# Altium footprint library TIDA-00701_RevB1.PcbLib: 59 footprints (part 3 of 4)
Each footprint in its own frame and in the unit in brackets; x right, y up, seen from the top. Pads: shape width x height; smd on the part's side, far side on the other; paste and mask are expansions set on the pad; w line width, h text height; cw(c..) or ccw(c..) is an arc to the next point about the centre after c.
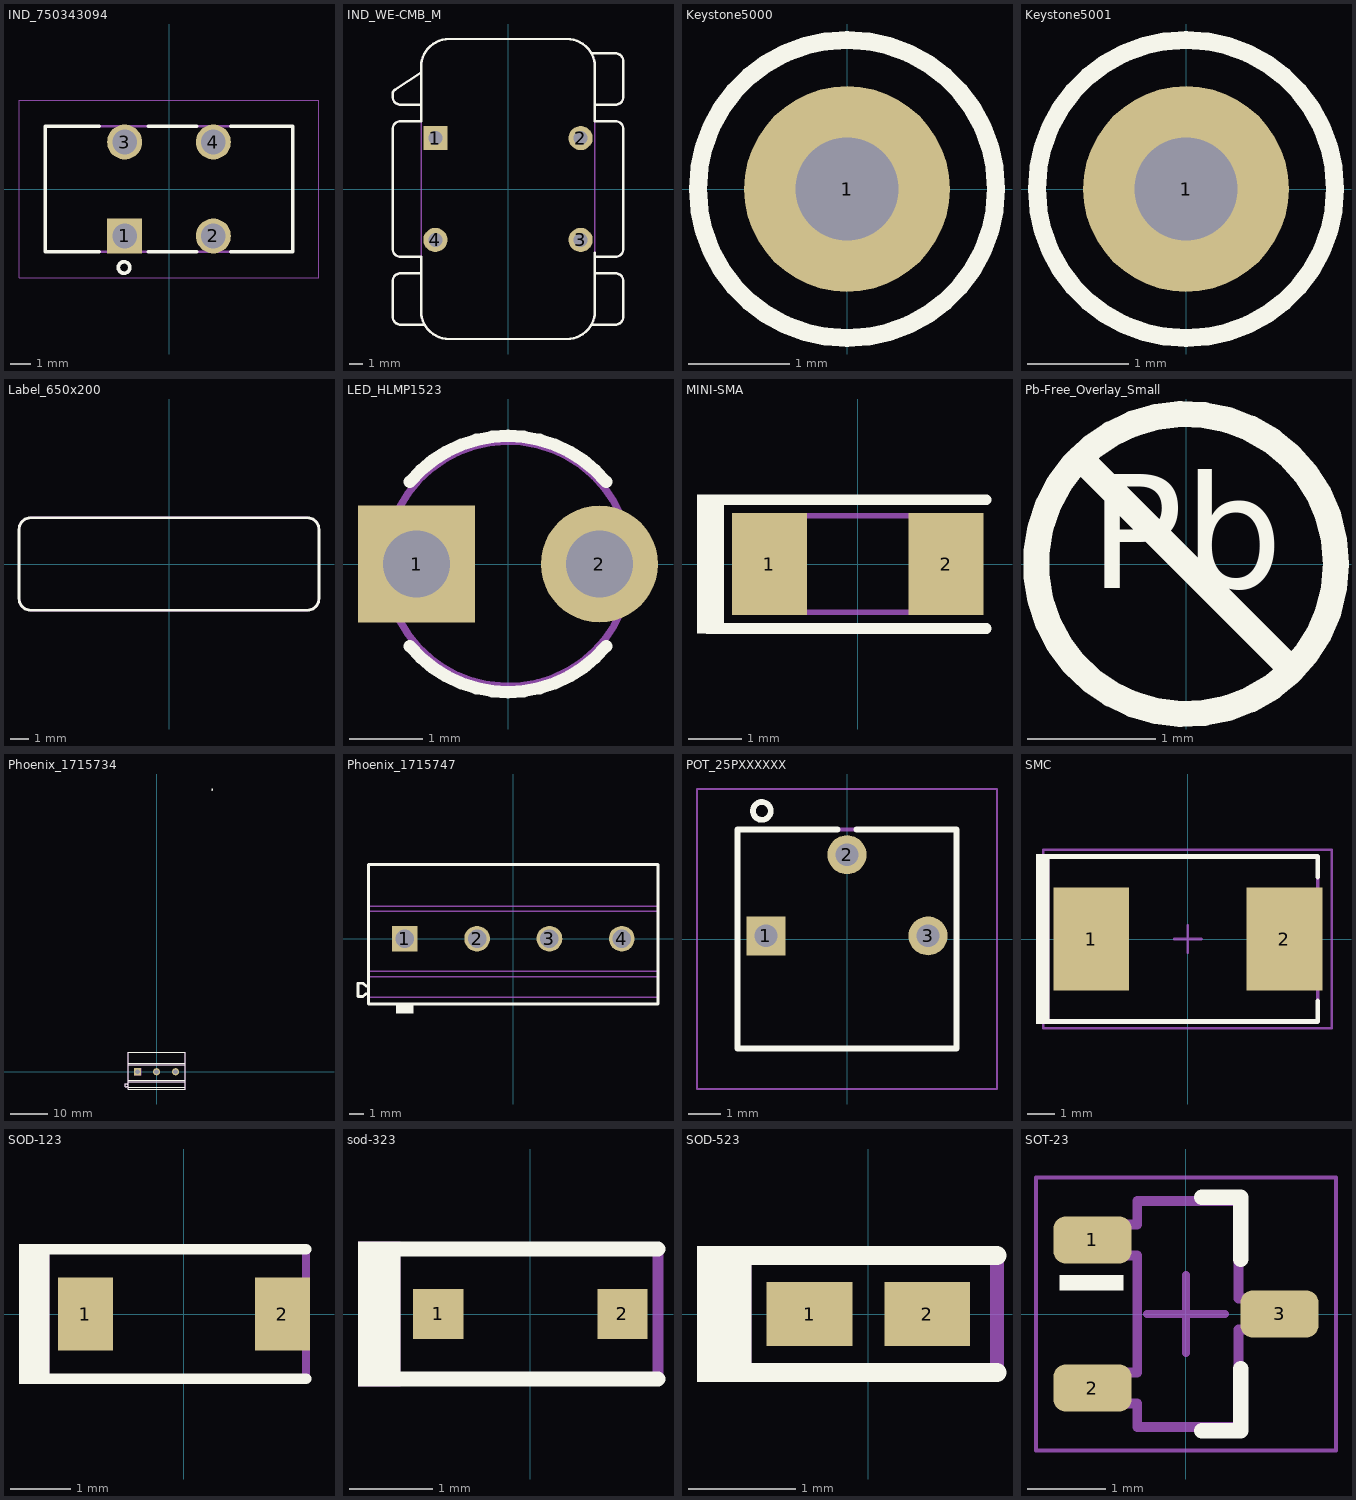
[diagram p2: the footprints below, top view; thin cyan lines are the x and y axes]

## IND_750343094 [mm] "INDUCTOR, TH-4P"
height 13.06
pads (4):
  rect 1.7x1.7 / inner round 1.7 / far side rect 1.7x1.7 hole 1.2: 1(-2.16,-2.285)
  round 1.7 hole 1.2: 2(2.16,-2.285) 3(-2.16,2.285) 4(2.16,2.285)
Top Overlay:
  circle w0.178: c-2.184,-3.82 r0.279
  lines w0.178: -3.4,-3.05 -6.03,-3.05 -6.03,3.05 -3.4,3.05 ; -1,-3.05 1.35,-3.05 ; -1,3.05 1.35,3.05 ; 3,-3.05 6.03,-3.05 6.03,3.05 3,3.05
Bottom Overlay:
  lines w0.178: -6.03,-3.048 -5.302,-3.048 ; -6.03,-1.966 -6.03,-0.95 ; -6.03,0.034 -6.03,1.05 ; -6.03,2.034 -6.03,3.05 -4.887,3.05 ; -4.445,-3.048 -3.302,-3.048 ; -4.03,3.05 -2.92,3.05 ; -1.35,3.05 1.27,3.048 ; -1,-3.05 1.35,-3.05 ; 2.92,-3.05 4.03,-3.05 ; 3.175,3.048 4.445,3.048 ; 4.887,-3.05 6.03,-3.05 6.03,-2.034 ; 5.302,3.048 6.03,3.048 ; 6.03,-1.05 6.03,-0.034 ; 6.03,0.95 6.03,1.966
Mechanical 5:
  circle w0.127: c-2.184,-3.82 r0.279
  lines w0.127: -6.03,-3.05 6.03,-3.05 6.03,3.05 -6.03,3.05 -6.03,-3.05
  text ".Designator" at -1.524,-0.508 h0.89
Mechanical 15:
  lines w0.05: -7.3,-4.32 7.3,-4.32 7.3,4.32 -7.3,4.32 -7.3,-4.32
Mechanical 17:
  text "LEAD LENGHT: 2.81MM" at -13.843,-6.604 h1.52
3D body: height 13.06, standoff 0, extent -6.03,-3.05 6.03,3.05

## IND_WE-CMB_M [mil] "Wurth"
height 1102.36
pads (4):
  rect 70x70 hole 40: 1(-210.63,147.64)
  round 70 hole 40: 2(210.63,147.64) 3(210.63,-147.64) 4(-210.63,-147.64)
Top Overlay:
  lines w7: -251.97,-354.33 ccw(c-171.26,-354.33) -171.26,-435.04 171.26,-435.04 ccw(c171.26,-354.33) 251.97,-354.33 251.97,-346.59 251.97,-323.7 251.97,-286.66 251.97,-237.09 251.97,-184.41 ; -251.97,-354.08 -251.97,-349.11 -251.97,-328.88 -251.97,-294.28 -251.97,-246.81 -251.97,-206.08 -251.97,-203.51 -251.97,-198.82 ; -251.97,-244.09 -311.02,-244.09 ccw(c-311.02,-267.72) -334.65,-267.72 -334.65,-370.08 ccw(c-311.02,-370.08) -311.02,-393.7 -241.67,-393.7 ; -251.97,-196.85 -311.02,-196.85 cw(c-311.02,-173.23) -334.65,-173.23 -334.65,173.23 cw(c-311.02,173.23) -311.02,196.85 -251.97,196.85 ; -251.97,198.82 -251.97,203.51 -251.97,206.08 -251.97,246.81 -251.97,294.28 -251.97,328.88 -251.97,349.11 -251.97,354.08 ; -251.97,244.09 -311.02,244.09 cw(c-311.02,267.72) -334.65,267.72 -334.65,274.98 cw(c-318.9,274.98) -327.56,288.13 -251.97,337.93 ; -251.97,354.33 cw(c-171.26,354.33) -171.26,435.04 171.26,435.04 cw(c171.26,354.33) 251.97,354.33 251.97,346.59 251.97,323.7 251.97,286.66 251.97,196.85 311.02,196.85 cw(c311.02,173.23) 334.65,173.23 334.65,-173.23 cw(c311.02,-173.23) 311.02,-196.85 251.97,-196.85 ; 241.71,-393.7 311.02,-393.7 ccw(c311.02,-370.08) 334.65,-370.08 334.65,-267.72 ccw(c311.02,-267.72) 311.02,-244.09 251.97,-244.09 ; 241.71,393.7 311.02,393.7 cw(c311.02,370.08) 334.65,370.08 334.65,267.72 cw(c311.02,267.72) 311.02,244.09 251.97,244.09
Mechanical 5:
  lines w5: -251.97,-354.33 ccw(c-171.26,-354.33) -171.26,-435.04 171.26,-435.04 ccw(c171.26,-354.33) 251.97,-354.33 251.97,-346.59 251.97,-323.7 251.97,-286.66 251.97,-237.09 251.97,-184.41 251.97,-165.23 251.97,237.09 251.97,286.66 251.97,323.7 251.97,346.59 251.97,354.33 ccw(c171.26,354.33) 171.26,435.04 -171.26,435.04 ccw(c-171.26,354.33) -251.97,354.33 ; -251.97,-354.08 -251.97,-349.11 -251.97,-328.88 -251.97,-294.28 -251.97,-246.81 -251.97,-206.08 -251.97,-203.51 -251.97,-198.82 -251.97,-165.23 -251.97,198.82 -251.97,203.51 -251.97,206.08 -251.97,246.81 -251.97,294.28 -251.97,328.88 -251.97,349.11 -251.97,354.08 ; -251.97,-244.09 -311.02,-244.09 ccw(c-311.02,-267.72) -334.65,-267.72 -334.65,-370.08 ccw(c-311.02,-370.08) -311.02,-393.7 -241.67,-393.7 ; -251.97,-196.85 -311.02,-196.85 cw(c-311.02,-173.23) -334.65,-173.23 -334.65,173.23 cw(c-311.02,173.23) -311.02,196.85 -251.97,196.85 ; -251.97,244.09 -311.02,244.09 cw(c-311.02,267.72) -334.65,267.72 -334.65,274.98 cw(c-318.9,274.98) -327.56,288.13 -251.97,337.93 ; 241.71,-393.7 311.02,-393.7 ccw(c311.02,-370.08) 334.65,-370.08 334.65,-267.72 ccw(c311.02,-267.72) 311.02,-244.09 251.97,-244.09 ; 241.71,393.7 311.02,393.7 cw(c311.02,370.08) 334.65,370.08 334.65,267.72 cw(c311.02,267.72) 311.02,244.09 251.97,244.09 ; 251.97,-196.85 311.02,-196.85 ccw(c311.02,-173.23) 334.65,-173.23 334.65,173.23 ccw(c311.02,173.23) 311.02,196.85 251.97,196.85
  text ".Designator" at 6,21 h35
3D body: height 1043.91, standoff -117.51, extent -334.65,-393.69 334.64,393.71

## Keystone5000 [mil] "For Keystone 500x miniature loop terminals"
height 181.1
pads (1):
  round 80 hole 40: 1(0,0)
Top Overlay:
  circle w7: c0,0 r58
Mechanical 5:
  circle w5: c0,0 r58.31
  text ".Designator" at -164,5 h35
3D body: height 181.97, standoff -118.11, extent -49,-49 49.04,49.24

## Keystone5001 [mil] "For Keystone 500x miniature loop terminals"
height 181.1
pads (1):
  round 80 hole 40: 1(0,0)
Top Overlay:
  circle w7: c0,0 r58
Mechanical 5:
  circle w5: c0,0 r58.31
  text ".Designator" at -105,66 h35
3D body: height 181.97, standoff -118.11, extent -49,-49 49.04,49.24

## Label_650x200 [mm] "Thermal Transfer Label"
height 0.025
Top Overlay:
  lines w0.152: -8.255,-1.905 ccw(c-7.62,-1.905) -7.62,-2.54 7.62,-2.54 ccw(c7.62,-1.905) 8.255,-1.905 8.255,1.905 ccw(c7.62,1.905) 7.62,2.54 -7.62,2.54 ccw(c-7.62,1.905) -8.255,1.905 -8.255,-1.905
Mechanical 5:
  lines w0.127: -8.255,-1.905 ccw(c-7.62,-1.905) -7.62,-2.54 7.62,-2.54 ccw(c7.62,-1.905) 8.255,-1.905 8.255,1.905 ccw(c7.62,1.905) 7.62,2.54 -7.62,2.54 ccw(c-7.62,1.905) -8.255,1.905 -8.255,-1.905
  text ".Designator" at -1.524,-0.508 h0.89
3D body: height 0.03, standoff 0, extent -8.268,-2.553 8.268,2.553

## LED_HLMP1523 [mm] "Everlight Electronics"
height 4.8
pads (2):
  rect 1.6x1.6 hole 0.914: 1(-1.25,0)
  round 1.6 hole 0.914: 2(1.25,0)
Top Overlay:
  lines w0.17: -1.341,-1.125 ccw(c0,0) 1.341,-1.125 ; -1.341,1.125 cw(c0,0) 1.341,1.125
Mechanical 5:
  lines w0.1: -1.57,-0.571 ccw(c0.004,0.002) -1.57,0.575 -1.57,-0.571
  text ".Designator" at 0.305,-0.635 h0.89
3D body: height 6.2, standoff -4.86, extent -1.6,-1.675 1.675,1.675

## MINI-SMA [mm] "COMCHIP"
height 1.45
pads (2):
  rect 1.4x1.9 smd: 1(-1.65,0) 2(1.65,0)
Top Overlay:
  rectangle: -2.999,-1.298 -2.5,1.302
  lines w0.2: -2.8,-1.2 2.4,-1.2 ; -2.8,1.2 2.4,1.2
Mechanical 5:
  rectangle: -1.999,-0.898 -1.299,0.902
  lines w0.1: -2,-0.9 -2,0.9 2,0.9 2,-0.9 0,-0.9 -1.5,-0.9 -2,-0.9
  text ".Designator" at 0.973,0.423 h0.89
3D body: height 1.7, standoff 0, extent -1.95,-0.9 1.95,0.9

## Pb-Free_Overlay_Small [mm]
Top Overlay:
  circle w0.203: c0,0 r1.168
  lines w0.203: -0.826,0.826 0.826,-0.826
  text "Pb" at -0.752,-0.48 h1.52

## Phoenix_1715734 [mm] "Phoenix"
height 13.8
pads (3):
  rect 1.9x1.9 hole 1.321: 1(-5.08,0)
  round 1.9 hole 1.321: 2(0,0) 3(5.08,0)
Top Overlay:
  circle w0.152: c14.834,75.362 r0.152
  lines w0.2: -7.62,-3.869 -7.787,-3.869 -8.019,-4.064 -8.361,-4.064 -8.361,-3.136 -8.019,-3.136 -7.787,-3.331 -7.62,-3.331 ; -7.62,-4.1 7.62,-4.1 ; -7.62,-4.1 -7.62,-4.6 7.62,-4.6 7.62,-4.1 ; -7.62,-4.1 -7.62,-2.672 ; -7.62,-2.672 7.62,-2.672 ; -7.62,-2.672 -7.62,-2.283 ; -7.62,-2.283 7.62,-2.283 ; -7.62,-2.283 -7.62,1.909 ; -7.62,1.909 7.62,1.909 ; -7.62,1.909 -7.62,2.29 ; -7.62,2.29 7.62,2.29 ; -7.62,2.29 -7.62,5.2 7.62,5.2 7.62,2.29 ; 7.62,-4.1 7.62,-2.672 ; 7.62,-2.672 7.62,-2.283 ; 7.62,-2.283 7.62,1.909 ; 7.62,1.909 7.62,2.29
Mechanical 5:
  region: -6.025,0.95 -4.125,0.95 -4.125,-0.95 -6.025,-0.95
  lines w0.127: -7.62,-3.869 -7.787,-3.869 -8.019,-4.064 -8.361,-4.064 -8.361,-3.136 -8.019,-3.136 -7.787,-3.331 -7.62,-3.331 ; -7.62,-4.1 -7.62,-2.672 ; -7.62,-4.1 -7.62,-4.6 7.62,-4.6 7.62,-4.1 ; -7.62,-4.1 7.62,-4.1 ; -7.62,-2.672 -7.62,-2.283 ; -7.62,-2.672 7.62,-2.672 ; -7.62,-2.283 -7.62,1.909 ; -7.62,-2.283 7.62,-2.283 ; -7.62,1.909 -7.62,2.29 ; -7.62,1.909 7.62,1.909 ; -7.62,2.29 -7.62,5.2 7.62,5.2 7.62,2.29 ; -7.62,2.29 7.62,2.29 ; 7.62,-4.1 7.62,-2.672 ; 7.62,-2.672 7.62,-2.283 ; 7.62,-2.283 7.62,1.909 ; 7.62,1.909 7.62,2.29
  text ".Designator" at -2.21,0.33 h0.89
3D body: height 14.2, standoff -3.5, extent -8.361,-4.6 7.62,5.2

## Phoenix_1715747 [mm] "Terminal Block, 5.08mm, 4x1, TH"
height 13.8
pads (4):
  rect 1.8x1.8 hole 1.3: 1(-7.62,0)
  round 1.8 hole 1.3: 2(-2.54,0) 3(2.54,0) 4(7.62,0)
Top Overlay:
  rectangle: -8.25,-5.25 -7,-4.599
  lines w0.2: -10.16,-3.869 -10.327,-3.869 -10.559,-4.064 -10.901,-4.064 -10.901,-3.136 -10.559,-3.136 -10.327,-3.331 -10.16,-3.331 ; -10.16,-4.6 -10.16,5.2 10.16,5.2 10.16,-4.6 -10.16,-4.6
Mechanical 5:
  lines w0.1: -10.16,-4.1 10.16,-4.1 ; -10.16,-3.869 -10.327,-3.869 -10.559,-4.064 -10.901,-4.064 -10.901,-3.136 -10.559,-3.136 -10.327,-3.331 -10.16,-3.331 ; -10.16,-2.672 10.16,-2.672 ; -10.16,-2.283 10.16,-2.283 ; -10.16,1.909 10.16,1.909 ; -10.16,2.29 10.16,2.29 ; -10.16,-4.6 10.16,-4.6 10.16,5.2 -10.16,5.2 -10.16,-4.6
  text ".Designator" at -0.559,0.66 h0.89
3D body: height 14.2, standoff -3.5, extent -10.901,-4.6 10.16,5.2

## POT_25PXXXXXX [mm] "Potentiometer, 25p series, through hole, 3 pin"
height 5.13
pads (3):
  rect 1.222x1.222 hole 0.714: 1(-2.54,0.1)
  round 1.222 hole 0.714: 2(0,2.64) 3(2.54,0.1)
Top Overlay:
  circle w0.178: c-2.667,4.013 r0.279
  lines w0.178: -0.3,3.43 -3.43,3.43 -3.43,-3.43 3.43,-3.43 3.43,3.43 0.3,3.43
  text ".Designator" at 3.708,0.737 h0.89
Mechanical 5:
  circle w0.127: c-2.54,0.1 r0.279
  lines w0.127: -3.43,-3.43 -3.43,3.43 3.43,3.43 3.43,-3.43 -3.43,-3.43
  text ".Designator" at -0.178,1.295 h0.89
Mechanical 15:
  lines w0.05: -4.7,-4.7 -4.7,4.7 4.7,4.7 4.7,-4.7 -4.7,-4.7
Mechanical 17:
  text "Lead Length : 5.08  +/- 1.01mm" at -12.954,1.778 h1.02
3D body: height 5.13, standoff 0, extent -3.43,-3.43 3.43,3.43

## SMC [mil] "Molded Diode, 2-Leads, Body 6.9x5.8mm, IPC Medium Density, based on OnSemi component dimensions and land patterns"
height 94.88
pads (2):
  rect 110x150 smd: 1(-140.49,0) 2(140.49,0)
Top Overlay:
  rectangle: -221,-123.5 -201,123.5
  lines w7: -210,-120 189,-120 189,-90.25 ; -210,120 189,120 189,90.25
Mechanical 5:
  rectangle: -221,-123.5 -201,123.5
  lines w5: -210,-120 189,-120 189,120 -210,120
  text ".Designator" at -14,-44 h40
Mechanical 15:
  lines w3.94: -19.69,0 19.68,0 ; 0,-19.68 0,19.68 ; -210.46,-129.92 -210.46,129.92 209.38,129.92 209.38,-129.92 -210.46,-129.92
3D body: height 91.35, standoff 0.6, extent -156.49,-116.14 156.5,116.15

## SOD-123 [mm] "On Semi recommended land pattern"
height 1.35
pads (2):
  rect 0.915x1.22 smd: 1(-1.637,0) 2(1.637,0)
Top Overlay:
  rectangle: -2.743,-1.168 -2.235,1.168
  lines w0.178: -2.413,-1.079 2.032,-1.079 ; -2.413,1.079 2.032,1.079
Mechanical 5:
  rectangle: -2.743,-1.168 -2.235,1.168
  lines w0.127: -2.413,-1.079 2.032,-1.079 2.032,1.079 -2.413,1.079
  text ".Designator" at -1.143,-0.33 h0.89
3D body: height 1.35, standoff 0, extent -1.932,-0.9 1.932,0.9

## sod-323 [mm] "NXP recommended land pattern"
height 1.15
pads (2):
  rect 0.6x0.6 smd paste-0.05: 1(-1.1,0) 2(1.1,0)
Top Overlay:
  rectangle: -2.057,-0.864 -1.549,0.864
  lines w0.178: -1.803,-0.775 0.1,-0.775 1.525,-0.775 ; -1.803,0.775 0.1,0.775 1.525,0.775
Mechanical 5:
  rectangle: -2.057,-0.864 -1.549,0.864
  lines w0.127: -1.803,-0.775 0.1,-0.775 1.525,-0.775 1.525,0.775 0.1,0.775 -1.803,0.775
  text ".Designator" at 0.711,0.432 h0.89
3D body: height 1.1, standoff 0, extent -1.3,-0.675 1.3,0.675

## SOD-523 [mm] "NXP Semiconductor recommended land pattern, nominal STEP model"
height 0.7
pads (2):
  rect 0.8x0.6 smd paste-0.05: 1(-0.55,0) 2(0.55,0)
Top Overlay:
  rectangle: -1.6,-0.635 -1.092,0.635
  lines w0.178: -1.475,-0.546 0,-0.546 1.2,-0.546 ; -1.475,0.546 0,0.546 1.2,0.546
Mechanical 5:
  rectangle: -1.6,-0.635 -1.092,0.635
  lines w0.127: -1.475,-0.546 0,-0.546 1.2,-0.546 1.2,0.546 0,0.546 -1.475,0.546
  text ".Designator" at 0.279,-0.838 h0.89
3D body: height 0.72, standoff 0.02, extent -0.8,-0.399 0.8,0.399

## SOT-23 [mm] "SOT23, 3-Leads, Body 2.9x1.3mm, Pitch 0.95mm, Lead Span 2.5mm, IPC Medium Density"
height 1.1
pads (3):
  rrect50% 1x0.6 smd: 1(-1.2,0.95) 2(-1.2,-0.95) 3(1.2,0)
Top Overlay:
  rectangle: -1.625,0.301 -0.8,0.501
  lines w0.2: 0.2,-1.5 0.7,-1.5 0.7,-0.7 ; 0.2,1.5 0.7,1.5 0.7,0.7
Mechanical 5:
  lines w0.127: -1.16,-1.15 -1.16,-0.75 -0.625,-0.75 -0.625,0.75 -1.16,0.75 -1.16,1.15 -0.625,1.15 -0.625,1.45 0.675,1.45 0.675,0.2 1.21,0.2 1.21,-0.2 0.675,-0.2 0.675,-1.45 -0.625,-1.45 -0.625,-1.15 -1.16,-1.15
  text ".Designator" at -0.406,0.406 h0.89
Mechanical 15:
  lines w0.05: -1.925,-1.75 1.925,-1.75 1.925,1.75 -1.925,1.75 -1.925,-1.75
  lines w0.1: -0.5,0 0.5,0 ; 0,-0.5 0,0.5
3D body: height 1, standoff 0, extent -1.16,-1.45 1.21,1.45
